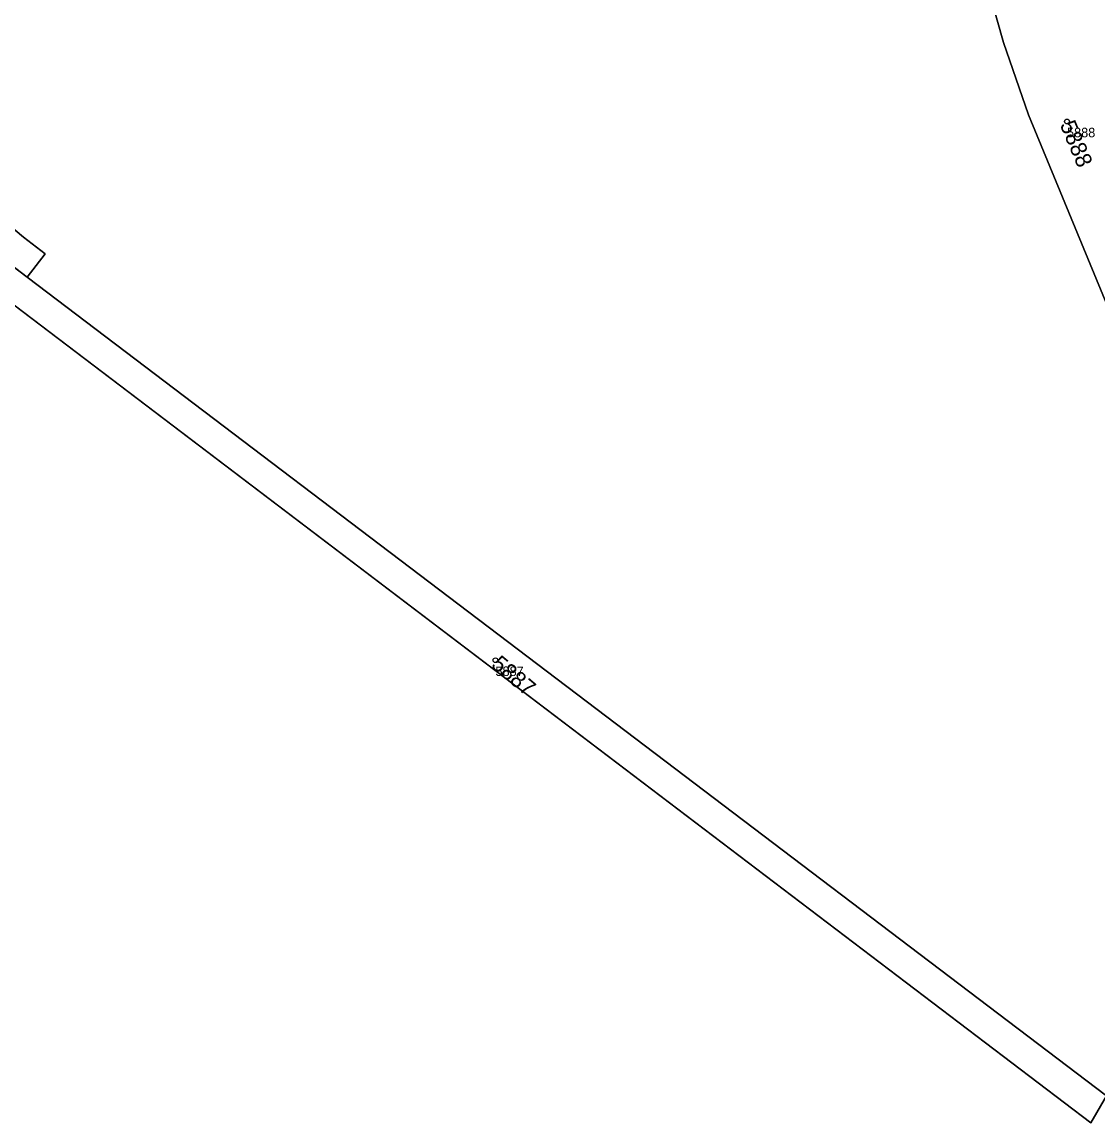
# Model space of a CAD drawing. Extents: x -690132 to -685994, y -975441 to -972444.
# Drawn here: x -687983.6 to -687870.4, y -975230.5 to -975114.6 of the extents above; entities that cross this region are included whole.
import ezdxf

# ---------------------------------------------------------------- set-up
doc = ezdxf.new("R2010")
doc.units = 0
for name, color, linetype in [('Definiční body', 7, 'Continuous'), ('Hranice parcel', 7, 'Continuous'), ('Parcelní čísla', 7, 'Continuous'), ('Polygon ku', 7, 'Continuous'), ('Polygon parcely', 7, 'Continuous')]:
    doc.layers.add(name, color=color, linetype=linetype)

msp = doc.modelspace()

# ---------------------------------------------------------------- linework, layer by layer
at = {"layer": 'Definiční body'}
for centre in [(-687873.7, -975125.11), (-687933.81, -975181.78)]:
    msp.add_circle(centre, 0.25, dxfattribs=at)
at = {"layer": 'Hranice parcel'}
for p, q in [((-687983.04, -975141.49), (-688002.42, -975126.78)), ((-687871.2, -975230.46), (-688004.74, -975128.99)), ((-687981.16, -975139.03), (-687983.04, -975141.49)), ((-687983.04, -975141.49), (-687869.56, -975227.62)), ((-687869.56, -975227.62), (-687871.2, -975230.46))]:
    msp.add_line(p, q, dxfattribs=at)
for points in [[(-687858.57, -975188.27), (-687859.09, -975180.71), (-687859.93, -975173.43), (-687861.53, -975165.82), (-687863.81, -975158.67), (-687866.35, -975152.02), (-687877.74, -975124.4), (-687880.38, -975116.79), (-687882.46, -975109.46), (-687883.81, -975098.11), (-687884.16, -975095.16), (-687884.2, -975094.81), (-687884.31, -975087.14), (-687882.82, -975072.15), (-687881.87, -975065.58), (-687880.57, -975056.58), (-687879.17, -975048.95), (-687876.94, -975041.42), (-687874.54, -975034.56), (-687871.66, -975028.07), (-687868.21, -975023.16)], [(-687988.91, -975110.15), (-687990.53, -975112.18), (-687991.25, -975113.65), (-687991.6, -975114.83), (-687991.79, -975116.47), (-687991.67, -975117.87), (-687991.3, -975119.81), (-687990.41, -975123.38), (-687989.39, -975126.48), (-687988.3, -975129.24), (-687987.54, -975130.71), (-687987, -975131.5), (-687986.4, -975132.24), (-687987.82, -975133.45), (-687987.23, -975134.11), (-687983.46, -975137.29), (-687981.16, -975139.03)]]:
    msp.add_lwpolyline(points, dxfattribs=at)
at = {"layer": 'Polygon ku'}
msp.add_lwpolyline([(-688004.74, -975128.99), (-687871.2, -975230.46), (-687869.56, -975227.62)], dxfattribs=at)
at = {"layer": 'Polygon parcely'}
for points in [[(-687866.35, -975152.02), (-687877.74, -975124.4), (-687880.38, -975116.79), (-687882.46, -975109.46), (-687883.81, -975098.11), (-687884.16, -975095.16), (-687884.2, -975094.81), (-687884.31, -975087.14), (-687882.82, -975072.15), (-687881.87, -975065.58), (-687880.57, -975056.58), (-687879.17, -975048.95), (-687876.94, -975041.42), (-687874.54, -975034.56), (-687871.66, -975028.07), (-687868.21, -975023.16)], [(-687868.21, -975023.16), (-687871.66, -975028.07), (-687874.54, -975034.56), (-687876.94, -975041.42), (-687879.17, -975048.95), (-687880.57, -975056.58), (-687881.87, -975065.58), (-687882.82, -975072.15), (-687884.31, -975087.14), (-687884.2, -975094.81), (-687884.16, -975095.16), (-687883.81, -975098.11), (-687882.46, -975109.46), (-687880.38, -975116.79), (-687877.74, -975124.4), (-687866.35, -975152.02)], [(-687987.23, -975134.11), (-687983.46, -975137.29), (-687981.16, -975139.03), (-687983.04, -975141.49), (-687869.56, -975227.62)]]:
    msp.add_lwpolyline(points, dxfattribs=at)
for points in [[(-687988.91, -975110.15), (-687995.07, -975115.66), (-687996.5, -975117.49), (-687996.82, -975119.78), (-687996.98, -975121.67), (-687999.14, -975123.66), (-688002.42, -975126.78), (-687983.04, -975141.49), (-687981.16, -975139.03), (-687983.46, -975137.29), (-687987.23, -975134.11), (-687987.82, -975133.45), (-687986.4, -975132.24), (-687987, -975131.5), (-687987.54, -975130.71), (-687988.3, -975129.24), (-687989.39, -975126.48), (-687990.41, -975123.38), (-687991.3, -975119.81), (-687991.67, -975117.87), (-687991.79, -975116.47), (-687991.6, -975114.83), (-687991.25, -975113.65), (-687990.53, -975112.18)], [(-687983.04, -975141.49), (-688002.42, -975126.78), (-688004.74, -975128.99), (-687871.2, -975230.46), (-687869.56, -975227.62)]]:
    msp.add_lwpolyline(points, close=True, dxfattribs=at)

# ---------------------------------------------------------------- texts
at = {"layer": 'Definiční body'}
for s, p in [('5888', (-687873.7, -975126.77)), ('5887', (-687933.81, -975183.44))]:
    msp.add_text(s, height=1, dxfattribs=at).set_placement(p)
at = {"layer": 'Parcelní čísla'}
for s, rotation, p in [('5888', 293, (-687874.48, -975125.44)), ('5887', 320, (-687934.36, -975182.43))]:
    msp.add_text(s, height=1.7, rotation=rotation, dxfattribs=at).set_placement(p)

doc.saveas('drawing.dxf')
